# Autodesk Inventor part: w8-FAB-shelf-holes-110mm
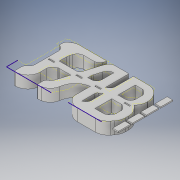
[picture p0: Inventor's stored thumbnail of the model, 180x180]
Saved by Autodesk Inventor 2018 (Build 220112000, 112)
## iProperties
Created: 2018-03
Part Number: w8-FAB-shelf-holes-110mm
Material: Generic
Document SubType Name: Modeling
Designer: katin
Density: 1 g/cm^3
Appearance: Default
Author: katin
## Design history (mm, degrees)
sketch "Sketch1"
  geometry: L1 (0, -103.188)-(-76.2, -103.188); L2 (-382.588, -407.987)-(-201.613, -407.987); L3 (-201.613, -407.987)-(-179.387, -330.2); L4 (-179.387, -330.2)-(-179.387, -303.315); L5 (-179.387, -303.315)-(-382.588, -303.315); L6 (-382.588, -303.315)-(-382.588, -330.2); L7 (-382.588, -330.2)-(-404.813, -407.987); L8 (-404.813, -407.987)-(-446.104, -500); L9 (-914.4, -410.18)-(-914.4, -330.2); L10 (-914.4, -330.2)-(-863.6, -279.4); L11 (-863.6, -279.4)-(-941.188, -201.812); L12 (-941.188, -100.013)-(-863.6, 0); L13 (-611.188, -500)-(-611.188, -274.637); L14 (-660.987, -274.638)-(-660.987, -501.799); L15 (-660.987, -203.2)-(-660.987, -104.775); L16 (-611.188, -104.775)-(-660.987, -104.775); L17 (-458.721, -302.879)-(-458.721, -330.2); L18 (-458.721, -330.2)-(-480.946, -407.987); L19 (-480.946, -407.987)-(-534.987, -407.987); L20 (-534.987, -407.987)-(-534.988, -302.879); L21 (-534.988, -302.879)-(-458.721, -302.879); L22 (-180.346, -201.117)-(-180.346, -104.775); L23 (-180.346, -104.775)-(-330, -104.775); L24 (-180.346, -201.117)-(-380.371, -201.117); L25 (-380.371, -201.117)-(-330, -104.775); L26 (-458.721, -201.117)-(-458.721, -104.775); L27 (-458.721, -201.117)-(-534.987, -201.117); L28 (-534.987, -201.117)-(-534.987, -104.775); L29 (-739.719, -407.987)-(-739.719, -306.388); L30 (-739.719, -407.987)-(-815.975, -407.987); L31 (-841.375, -354.012)-(-841.375, -381); L32 (-841.375, -381)-(-815.975, -407.987); L33 (-382.588, -407.987)-(-424.795, -502.08); L34 (-79.965, -502.08)-(-424.795, -502.08); L35 (-611.188, -104.775)-(-611.188, -203.2); L36 (-611.188, -500)-(-446.104, -500); L37 (0, -103.188)-(0, 0); L38 (-941.188, -201.812)-(-941.188, -100.013); L39 (0, -103.188)-(0, 0); L40 (0, 0)-(-406.4, 0); L41 (-406.4, 0)-(-458.721, -104.775); L42 (-534.987, -104.775)-(-558.8, 0); L43 (-611.188, -203.2)-(-660.987, -233.363); L44 (-660.987, -233.363)-(-660.987, -203.2); L45 (-558.8, 0)-(-863.6, 0); L46 (0, 0)-(-406.4, 0); L47 (-79.965, -502.08)-(-50.58, -485.849); L48 (-50.58, -485.849)-(-50.58, -407.987); L49 (-50.58, -407.987)-(-76.2, -407.987); L50 (-76.2, -407.987)-(-76.2, -103.188); L51 (-841.375, -354.012)-(-793.75, -306.388); L52 (-793.75, -306.388)-(-739.719, -306.388); L53 (-611.188, -274.637)-(-660.987, -274.638); L54 (-739.762, -201.612)-(-739.762, -103.187); L55 (-739.762, -103.187)-(-836.612, -103.188); L56 (-836.612, -103.188)-(-863.6, -138.112); L57 (-863.6, -138.112)-(-863.6, -176.213); L58 (-863.6, -176.213)-(-838.2, -201.612); L59 (-838.2, -201.612)-(-739.762, -201.612); L60 (-914.4, -410.18)-(-838.2, -501.799); L61 (-838.2, -501.799)-(-660.987, -501.799); L62 (0, 0)-(-406.4, 0); L63 (-558.8, 0)-(-863.6, 0)
  constraints: 126 end point, 13 perpendicular, 13 point on line, 10 vertical, 9 horizontal, 3 collinear, 1 parallel
sketch "Sketch2"
  geometry: L1 (0, 0)-(-940, 0); L2 (-940, 0)-(-940, -500); L3 (-940, -500)-(0, -500); L4 (0, -500)-(0, 0)
  constraints: 8 end point, 2 parallel, 1 horizontal, 1 perpendicular
  dimensions: "d10" = 940 distance of L3.end L2.end; "d11" = 500 distance of L2.end L1.end
extrude "Extrusion2" new body sketch "Sketch2" distance "d12" = 110; taper "d13" = 0 deg
sketch "Sketch3"
  geometry: L1 (0, 0)-(0, 500) reference; L2 (0, 408.758)-(113.674, 408.758); L3 (113.674, 408.758)-(113.674, 94.825); L4 (113.674, 94.825)-(0, 94.825); L5 (0, 94.825)-(0, 408.758); L6 (611.188, 500.062)-(650.182, 500.062); L7 (650.182, 500.062)-(650.182, 287.702); L8 (650.182, 287.702)-(611.188, 287.702); L9 (611.188, 287.702)-(611.188, 500.062); L10 (0, 500)-(129.919, 500); L11 (0, 500)-(940, 500) reference; L12 (129.919, 500)-(0, 408.758); L13 (0, 500)-(0, 408.758); L14 (739.775, 406.4)-(739.775, 307.975); L15 (739.775, 307.975)-(793.75, 307.975); L16 (793.75, 307.975)-(836.612, 350.838); L17 (836.612, 350.838)-(841.375, 355.6); L18 (841.375, 355.6)-(841.375, 381); L19 (841.375, 381)-(806.218, 418.355); L20 (806.218, 418.355)-(739.775, 418.355); L21 (739.775, 418.355)-(739.775, 406.4)
  constraints: 38 end point, 6 parallel, 4 perpendicular, 4 point on line, 2 horizontal, 1 collinear, 1 vertical
extrude "Extrusion3" cut sketch "Sketch3" distance "d14" = 150; taper "d15" = 0 deg
sketch "Sketch4"
  geometry: L1 (0, 500)-(940, 500) reference; L2 (839.788, 500)-(914.4, 411.163); L3 (914.4, 411.163)-(914.4, 310.193); L4 (914.4, 310.193)-(880.473, 275.82); L5 (880.473, 275.82)-(940, 217.064); L6 (940, 217.064)-(940, 500); L7 (940, 500)-(839.788, 500); L8 (940, 0)-(940, 500) reference; L9 (940, 99.14)-(940, 0); L10 (940, 0)-(863.6, 0); L11 (0, 0)-(940, 0) reference; L12 (940, 99.14)-(863.6, 0); L13 (728.744, 226.212)-(728.744, 72.721); L14 (728.744, 72.721)-(830.691, 72.721); L15 (830.691, 72.721)-(864.394, 116.456); L16 (864.394, 116.456)-(864.405, 192.017); L17 (864.405, 192.017)-(829.761, 226.212); L18 (829.761, 226.212)-(728.744, 226.212); L19 (649.575, 72.721)-(649.575, 226.081); L20 (649.575, 226.081)-(611.188, 202.869); L21 (611.188, 202.869)-(611.188, 72.721); L22 (611.188, 72.721)-(649.575, 72.721); L23 (727.378, 439.44)-(727.378, 283.141); L24 (727.378, 283.141)-(801.955, 283.141); L25 (801.955, 283.141)-(841.375, 322.561); L26 (841.375, 322.561)-(841.375, 403.65); L27 (841.375, 403.65)-(807.69, 439.44); L28 (807.69, 439.44)-(727.378, 439.44); L29 (534.987, 283.141)-(534.987, 439.44); L30 (534.987, 439.44)-(490.381, 439.44); L31 (490.381, 439.44)-(455.193, 321.307); L32 (455.193, 321.307)-(455.193, 283.141); L33 (455.193, 283.141)-(534.987, 283.141); L34 (534.987, 226.027)-(534.987, 72.721); L35 (534.987, 72.721)-(560.388, 0); L36 (560.388, 0)-(405.603, 0); L37 (455.193, 72.721)-(405.603, 0); L38 (455.193, 72.721)-(455.193, 226.027); L39 (455.193, 226.027)-(534.987, 226.027); L40 (250.031, 72.721)-(195.665, 72.721); L41 (195.665, 72.721)-(195.665, 226.027); L42 (195.665, 226.027)-(354.575, 226.027); L43 (354.575, 226.027)-(250.031, 72.721); L44 (195.665, 283.141)-(195.665, 362.436); L45 (195.665, 362.436)-(218.603, 439.44); L46 (218.603, 439.44)-(389.781, 439.44); L47 (389.781, 439.44)-(415.52, 500); L48 (415.52, 500)-(447.675, 500); L49 (611.188, 500)-(129.919, 500) reference; L50 (195.665, 283.141)-(380.412, 283.141); L51 (380.412, 283.141)-(380.412, 300.037); L52 (380.412, 300.037)-(421.936, 439.44); L53 (421.936, 439.44)-(447.675, 500); L54 (415.52, 500)-(447.675, 500); 1 further point
  constraints: 100 end point, 28 point on line, 12 perpendicular, 11 parallel, 3 vertical, 2 collinear
extrude "Extrusion4" cut sketch "Sketch4" distance "d16" = 150; taper "d17" = 0 deg
fillet "Fillet1" dims "d18" = 50
fillet "Fillet2" dims "d19" = 50
fillet "Fillet3" dims "d20" = 50
fillet "Fillet4" dims "d21" = 60
fillet "Fillet7" dims "d24" = 30
fillet "Fillet8" dims "d25" = 50
fillet "Fillet9" dims "d26" = 50
fillet "Fillet10" dims "d27" = 50
fillet "Fillet13" dims "d30" = 40
fillet "Fillet14" dims "d31" = 120
fillet "Fillet15" dims "d32" = 120
fillet "Fillet16" dims "d33" = 120
fillet "Fillet17" dims "d34" = 50
fillet "Fillet18" dims "d35" = 50
fillet "Fillet19" dims "d36" = 170
fillet "Fillet20" dims "d37" = 65
fillet "Fillet21" dims "d38" = 50
fillet "Fillet22" dims "d39" = 5
fillet "Fillet25" dims "d42" = 25
fillet "Fillet26" dims "d43" = 50
fillet "Fillet27" dims "d44" = 90
sketch "Sketch5"
  geometry: L1 (195.665, 72.721)-(195.665, 0); L2 (195.665, 0)-(278.632, 0); L3 (0, 0)-(285.193, 0) reference; L4 (278.632, 80.606)-(278.632, 0); L5 (278.632, 80.606)-(278.632, 104.775); L6 (223.608, 72.721)-(195.665, 72.721) reference; L7 (278.632, 104.775)-(195.665, 72.721)
  constraints: 10 end point, 2 vertical, 1 perpendicular, 1 point on line
extrude "Extrusion5" cut sketch "Sketch5" distance "d45" = 150; taper "d46" = 0 deg
sketch "Sketch6"
  geometry: L1 (463.037, 222.547)-(398.463, 127.297); L2 (398.463, 127.297)-(398.463, 22.263); L3 (455.193, 283.141)-(455.193, 311.832) reference; L4 (398.463, 22.263)-(534.988, 22.263); L5 (534.987, 226.027)-(534.987, 72.721) reference; L6 (534.988, 22.263)-(534.987, 226.027); L7 (534.987, 226.027)-(463.037, 222.547); 2 further points
  constraints: 10 end point, 2 perpendicular, 1 parallel
extrude "Extrusion6" cut sketch "Sketch6" distance "d48" = 150; taper "d49" = 0 deg
fillet "Fillet29" dims "d50" = 100
fillet "Fillet30" dims "d51" = 40
sketch "Sketch7"
  geometry: L1 (242.804, 83.41)-(242.804, 226.022); L2 (242.804, 226.022)-(357.713, 226.022); L3 (306.387, 83.41)-(242.804, 83.41); L4 (357.713, 226.022)-(313.861, 83.41); L5 (313.861, 83.41)-(242.804, 83.41); 1 further point
  constraints: 10 end point, 1 horizontal, 1 parallel, 1 perpendicular, 1 vertical
extrude "Extrusion7" cut sketch "Sketch7" distance "d52" = 150; taper "d53" = 0 deg
fillet "Fillet31" dims "d54" = 40
sketch "Sketch8"
  geometry: L1 (505.193, 226.027)-(534.987, 226.027) reference; L2 (534.987, 226.027)-(534.987, 72.721) reference; L3 (534.987, 127.541)-(534.987, 226.027); L4 (403.342, 127.541)-(534.987, 127.541); L5 (534.987, 226.027)-(435.488, 226.027); L6 (435.488, 226.027)-(403.342, 127.541); A1 r 100 centre (498.406, 96.512) between (415.634, 152.627) and (398.434, 98.891) reference; A2 r 100 centre (498.406, 96.512) between (415.634, 152.627) and (398.434, 98.891) reference; 2 further points
  constraints: 8 end point, 2 horizontal, 1 point on circle, 1 point on line, 1 tangent, 1 vertical
extrude "Extrusion8" cut sketch "Sketch8" distance "d55" = 150; taper "d56" = 0 deg
fillet "Fillet32" dims "d57" = 160
sketch "Sketch9"
  geometry: L1 (841.375, 322.561)-(801.955, 283.141) reference; L2 (841.375, 322.561)-(841.375, 298.749); L3 (841.375, 298.749)-(842.323, 283.141); L4 (842.323, 283.141)-(801.955, 283.141); 1 further point
  constraints: 6 end point, 1 perpendicular, 1 vertical
extrude "Extrusion9" cut sketch "Sketch9" distance "d58" = 150; taper "d59" = 0 deg
fillet "Fillet33" dims "d60" = 50
fillet "Fillet34" dims "d61" = 110
fillet "Fillet43" dims "d70" = 50
fillet "Fillet44" dims "d71" = 5
fillet "Fillet45" dims "d72" = 40
sketch "Sketch10"
  geometry: L1 (-1.587, 508)-(69.85, 508); L2 (69.85, 508)-(69.85, -22.225); L3 (69.85, -22.225)-(-1.587, -22.225); L4 (-1.587, -22.225)-(-1.587, 508); 1 further point
  constraints: 8 end point, 2 parallel, 1 horizontal, 1 perpendicular
extrude "Extrusion10" cut sketch "Sketch10" distance "d73" = 150; taper "d74" = 0 deg
fillet "Fillet46" dims "d75" = 40
fillet "Fillet47" dims "d76" = 5
fillet "Fillet48" dims "d77" = 5
fillet "Fillet49" dims "d78" = 5
sketch "Sketch12"
  geometry: C1 r 5 at (151.971, -436.562); C2 r 5 at (858.837, -436.562); 1 further point
  constraints: 2 centre point
  dimensions: "d85" = 10 diameter of C1; "d86" = 10 diameter of C2
extrude "Extrusion11" cut sketch "Sketch12" distance "d89" = 24; taper "d90" = 0 deg
sketch "Sketch13"
  geometry: L1 (151.971, -444.562)-(151.971, -428.562); L2 (155.971, -444.562)-(155.971, -428.562); L3 (147.971, -428.562)-(147.971, -444.562); L4 (151.971, -436.562)-(167.971, -436.562); L5 (858.838, -444.562)-(858.838, -428.562); L6 (862.838, -444.562)-(862.838, -428.562); L7 (854.837, -428.562)-(854.837, -444.562); C1 r 5 at (151.971, -436.562) reference; A1 r 4 centre (151.971, -444.562) between (147.971, -444.562) and (155.971, -444.562); A2 r 4 centre (151.971, -428.562) between (155.971, -428.562) and (147.971, -428.562); A3 r 4 centre (858.838, -444.562) between (854.837, -444.562) and (862.838, -444.562); A4 r 4 centre (858.838, -428.562) between (862.838, -428.562) and (854.837, -428.562); 1 further point
  constraints: 18 end point, 8 point on circle, 8 tangent, 4 centre point, 3 parallel, 2 midpoint, 1 horizontal, 1 perpendicular, 1 vertical
  dimensions: "d91" = 8 distance of L4.start L1.end; "d92" = 90 deg angle of L4 L1 (derived); "d93" = 8 diameter of A2; "d94" = 8 distance of point (858.838, -436.562) L5.end; "d95" = 8 diameter of A4
extrude "Extrusion12" cut sketch "Sketch13" distance "d96" = 24; taper "d97" = 0 deg
sketch "Sketch14"
  geometry: L1 (858.873, -439.675)-(858.873, -455.675); L2 (854.873, -439.675)-(854.873, -455.675); L3 (862.873, -455.675)-(862.873, -439.675); A1 r 4 centre (858.873, -439.675) between (862.873, -439.675) and (854.873, -439.675); A2 r 4 centre (858.873, -455.675) between (854.873, -455.675) and (862.873, -455.675); 2 further points
  constraints: 8 end point, 4 point on circle, 4 tangent, 2 centre point, 1 midpoint, 1 parallel, 1 vertical
  dimensions: "d98" = 8 distance of point (858.873, -447.675) L1.end; "d99" = 8 diameter of A2
extrude "Extrusion13" cut sketch "Sketch14" distance "d100" = 8; taper "d101" = 0 deg
sketch "Sketch15"
  geometry: L1 (151.995, -456.562)-(151.995, -440.562); L2 (155.995, -456.562)-(155.995, -440.562); L3 (147.995, -440.562)-(147.995, -456.562); A1 r 4 centre (151.971, -444.562) between (147.971, -444.562) and (155.971, -444.562) reference; A2 r 4 centre (151.995, -456.562) between (147.995, -456.562) and (155.995, -456.562); A3 r 4 centre (151.995, -440.562) between (155.995, -440.562) and (147.995, -440.562); 2 further points
  constraints: 8 end point, 5 point on circle, 4 tangent, 2 centre point, 1 midpoint, 1 parallel, 1 vertical
  dimensions: "d102" = 8 distance of point (151.995, -448.562) L1.end; "d103" = 8 diameter of A3
extrude "Extrusion14" cut sketch "Sketch15" distance "d104" = 8; taper "d105" = 0 deg
sketch "Sketch16"
  geometry: L1 (131.762, 258.023)-(181.762, 258.023); L2 (181.762, 258.023)-(181.762, 247.023); L3 (181.762, 247.023)-(131.762, 247.023); L4 (131.762, 247.023)-(131.762, 258.023); L5 (382.587, 258.023)-(432.587, 258.023); L6 (432.587, 258.023)-(432.587, 247.023); L7 (432.587, 247.023)-(382.587, 247.023); L8 (382.587, 247.023)-(382.587, 258.023); L9 (554.038, 258.023)-(604.038, 258.023); L10 (604.038, 258.023)-(604.038, 247.023); L11 (604.038, 247.023)-(554.038, 247.023); L12 (554.038, 247.023)-(554.038, 258.023); L13 (817.562, 258.023)-(867.562, 258.023); L14 (867.562, 258.023)-(867.562, 247.023); L15 (867.562, 247.023)-(817.562, 247.023); L16 (817.562, 247.023)-(817.562, 258.023); 1 further point
  constraints: 32 end point, 8 parallel, 4 horizontal, 4 perpendicular, 2 point on line
  dimensions: "d106" = 50 distance of L2.end L3.end; "d107" = 11 distance of L1.end L2.end; "d108" = 50 distance of L6.end L7.end; "d109" = 11 distance of L5.end L6.end; "d110" = 50 distance of L10.end L11.end; "d111" = 11 distance of L9.end L10.end; "d112" = 50 distance of L14.end L15.end; "d113" = 11 distance of L13.end L14.end
extrude "Extrusion15" cut sketch "Sketch16" distance "d114" = 110; taper "d115" = 0 deg
sketch "Sketch17"
  geometry: L1 (963.612, 0)-(1013.612, 0); L2 (1013.612, 0)-(1013.612, 110); L3 (1013.612, 110)-(963.612, 110); L4 (963.612, 110)-(963.612, 0); L5 (963.612, 127)-(1013.612, 127); L6 (1013.612, 127)-(1013.612, 237); L7 (1013.612, 237)-(963.612, 237); L8 (963.612, 237)-(963.612, 127); L9 (963.612, 254)-(1013.612, 254); L10 (1013.612, 254)-(1013.612, 364); L11 (1013.612, 364)-(963.612, 364); L12 (963.612, 364)-(963.612, 254); L13 (963.612, 382.587)-(1013.612, 382.587); L14 (1013.612, 382.587)-(1013.612, 492.587); L15 (1013.612, 492.587)-(963.612, 492.587); L16 (963.612, 492.587)-(963.612, 382.587); 1 further point
  constraints: 32 end point, 8 parallel, 4 horizontal, 4 perpendicular, 3 point on line
  dimensions: "d116" = 50 distance of L3.end L2.end; "d117" = 110 distance of L2.end L1.end; "d118" = 50 distance of L7.end L6.end; "d119" = 110 distance of L6.end L5.end; "d120" = 110 distance of L10.end L9.end; "d121" = 50 distance of L15.end L14.end; "d122" = 110 distance of L14.end L13.end
extrude "Extrusion16" join sketch "Sketch17" distance "d123" = 11; taper "d124" = 0 deg
body "Solid2"
